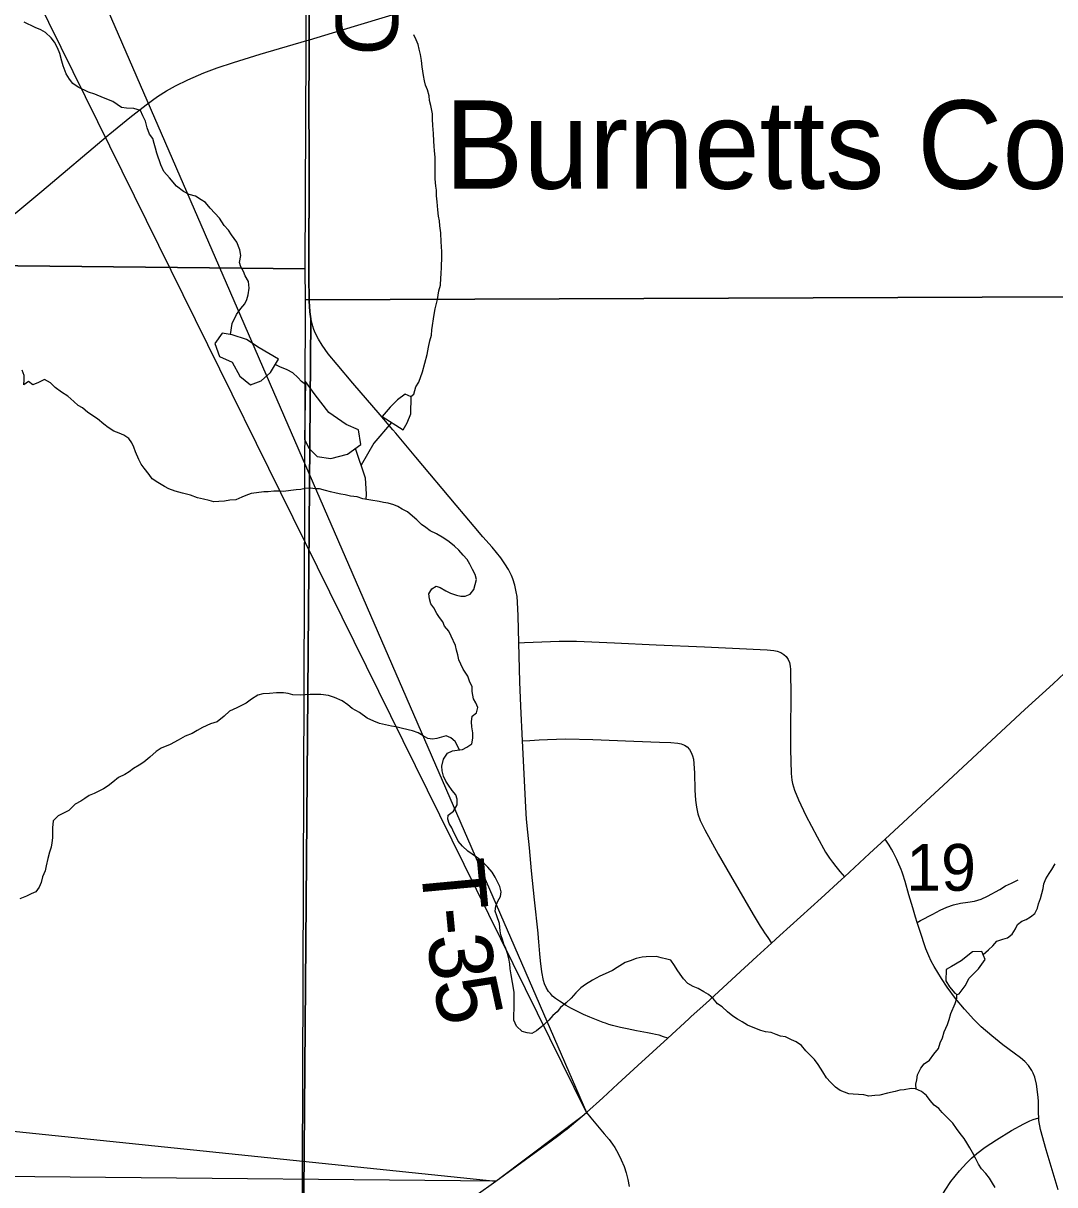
# Model space of a CAD drawing. Extents: x 0 to 34, y 0 to 22.
# Drawn here: x 5.524 to 6.446, y 17.466 to 18.505 of the extents above; entities that cross this region are included whole.
import ezdxf

# ---------------------------------------------------------------- set-up
doc = ezdxf.new("R2010")
doc.units = 0
for name, color, linetype in [('Default', 7, 'Continuous'), ('GM_X_Minor_Lake', 7, 'Continuous'), ('GM_X_Minor_River', 7, 'Continuous'), ('GM_X_Section', 7, 'Continuous'), ('GM_X_Section_Text', 7, 'Continuous'), ('GM_X_State_Route', 7, 'Continuous'), ('GM_X_Township_Road', 7, 'Continuous'), ('GM_X_Township_Road_Text', 7, 'Continuous'), ('GM_X_Unincorporated_Text', 7, 'Continuous'), ('SH_Text', 7, 'Continuous')]:
    doc.layers.add(name, color=color, linetype=linetype)

msp = doc.modelspace()

# ---------------------------------------------------------------- linework, layer by layer
at = {"layer": 'Default'}
for points in [[(5.415, 18.9404), (6.0271, 17.5311), (5.415, 18.772)], [(4.804, 17.5881), (5.946, 17.4698), (4.804, 17.4805)]]:
    msp.add_lwpolyline(points, close=True, dxfattribs=at)
at = {"layer": 'GM_X_Minor_Lake'}
for points in [[(5.7517, 18.2048), (5.7346, 18.2149), (5.7231, 18.2224), (5.7102, 18.2265), (5.7015, 18.2279), (5.6948, 18.2188), (5.699, 18.2071), (5.7104, 18.2022), (5.7173, 18.1897), (5.7268, 18.1819), (5.7363, 18.1853), (5.7446, 18.193)], [(5.7446, 18.193), (5.7517, 18.2048)], [(5.7749, 18.1329), (5.7791, 18.125), (5.7864, 18.1178), (5.7985, 18.116), (5.8136, 18.1199), (5.8253, 18.1284), (5.8233, 18.1416), (5.8123, 18.1465), (5.7967, 18.157), (5.7845, 18.1728), (5.776, 18.1849)], [(5.776, 18.1849), (5.7749, 18.1329)], [(5.8631, 18.1415), (5.8668, 18.148), (5.8702, 18.156), (5.8704, 18.1712), (5.8651, 18.1734), (5.8583, 18.1684), (5.8516, 18.1619), (5.8444, 18.1535)], [(5.8444, 18.1535), (5.8631, 18.1415)], [(6.3604, 17.6371), (6.3657, 17.6444), (6.3694, 17.6512), (6.3777, 17.6596), (6.3837, 17.668), (6.3806, 17.6752), (6.3723, 17.6748), (6.3621, 17.6667), (6.3534, 17.6617), (6.3489, 17.659), (6.3486, 17.6488), (6.3517, 17.6435)], [(6.3517, 17.6435), (6.3565, 17.6377), (6.3585, 17.6367), (6.3604, 17.6371)]]:
    msp.add_lwpolyline(points, dxfattribs=at)
at = {"layer": 'GM_X_Minor_River'}
for points in [[(5.7088, 18.2267), (5.7104, 18.2367), (5.7141, 18.2447), (5.7182, 18.2501), (5.7216, 18.2543), (5.7234, 18.2582), (5.7245, 18.2623), (5.7256, 18.2684), (5.7248, 18.2741), (5.722, 18.2794), (5.7205, 18.2832), (5.7181, 18.2873), (5.7169, 18.2911), (5.718, 18.2976), (5.7172, 18.3025), (5.7144, 18.3093), (5.7098, 18.3161), (5.707, 18.3202), (5.7032, 18.3244), (5.6989, 18.3308), (5.6908, 18.3398), (5.6866, 18.345), (5.6827, 18.3473), (5.6777, 18.3506), (5.672, 18.3521), (5.6667, 18.3546), (5.6605, 18.3595), (5.6543, 18.367), (5.6493, 18.3726), (5.6466, 18.3787), (5.643, 18.3889), (5.6418, 18.3934), (5.6406, 18.3976), (5.6394, 18.4021), (5.6363, 18.4059), (5.6344, 18.4116), (5.6328, 18.4176), (5.6304, 18.4225), (5.6284, 18.4271), (5.6223, 18.4289), (5.6159, 18.4292), (5.6113, 18.4299), (5.6036, 18.4351), (5.5952, 18.4384), (5.5876, 18.4417), (5.5818, 18.4435), (5.5727, 18.448), (5.568, 18.4513), (5.565, 18.4551), (5.5618, 18.46), (5.5591, 18.4672), (5.5579, 18.4713), (5.5563, 18.4781), (5.5543, 18.4831), (5.5516, 18.4883), (5.5485, 18.4921), (5.5435, 18.497), (5.5393, 18.4992), (5.5343, 18.5014), (5.5244, 18.5062)], [(5.8702, 18.1713), (5.8729, 18.1735), (5.8747, 18.18), (5.8773, 18.1842), (5.8806, 18.1934), (5.8846, 18.209), (5.886, 18.2155), (5.8871, 18.2212), (5.8885, 18.2262), (5.8889, 18.2311), (5.891, 18.2448), (5.892, 18.2498), (5.8938, 18.2582), (5.8952, 18.2658), (5.8967, 18.2711), (5.897, 18.2772), (5.8973, 18.281), (5.8976, 18.2871), (5.8979, 18.2962), (5.8978, 18.3004), (5.8974, 18.3057), (5.8973, 18.3095), (5.8969, 18.3178), (5.896, 18.3239), (5.8956, 18.3285), (5.8948, 18.3326), (5.8943, 18.3383), (5.8935, 18.3455), (5.893, 18.3508), (5.8929, 18.3558), (5.8925, 18.3596), (5.892, 18.366), (5.8919, 18.3808), (5.8918, 18.3854), (5.8913, 18.3911), (5.8909, 18.3952), (5.8908, 18.3998), (5.8904, 18.4066), (5.8899, 18.4138), (5.8894, 18.4195), (5.8894, 18.4241), (5.8881, 18.4317), (5.8869, 18.4362), (5.8865, 18.4404), (5.8849, 18.4457), (5.8833, 18.4498), (5.8822, 18.4536), (5.8813, 18.4586), (5.8801, 18.4661), (5.8796, 18.4718), (5.8788, 18.4771), (5.8776, 18.4821), (5.8768, 18.4862), (5.8748, 18.4904), (5.8729, 18.4949)], [(5.776, 18.182), (5.7723, 18.1847), (5.7692, 18.1885), (5.7646, 18.1926), (5.7596, 18.1952), (5.7531, 18.1978), (5.7488, 18.2)], [(5.8964, 18.0006), (5.9014, 17.9977), (5.9056, 17.9954), (5.911, 17.9936), (5.9148, 17.9929), (5.9186, 17.993), (5.9231, 17.9945), (5.9265, 17.9988), (5.9287, 18.0079), (5.9275, 18.0121), (5.9251, 18.0166), (5.9228, 18.0215), (5.9204, 18.0257), (5.917, 18.0294), (5.9131, 18.0339), (5.9092, 18.0377), (5.9043, 18.0414), (5.8996, 18.0447), (5.8931, 18.0485), (5.8874, 18.0514), (5.8835, 18.0544), (5.8797, 18.057), (5.8755, 18.0611), (5.8716, 18.0645), (5.867, 18.0682), (5.8624, 18.0708), (5.8586, 18.0731), (5.8548, 18.0745), (5.8498, 18.076), (5.8456, 18.0767), (5.8418, 18.0774), (5.8342, 18.0788), (5.8273, 18.0799), (5.822, 18.0817), (5.8162, 18.0824), (5.8113, 18.0835), (5.8075, 18.0842), (5.8033, 18.0849), (5.7983, 18.0863), (5.7937, 18.0874), (5.7884, 18.0888), (5.7846, 18.0888), (5.7804, 18.0895), (5.7755, 18.0891), (5.7717, 18.0882), (5.7675, 18.0878), (5.7629, 18.0874), (5.7561, 18.0865), (5.7523, 18.0868), (5.7477, 18.0868), (5.7424, 18.0863), (5.7386, 18.0863), (5.7322, 18.0854), (5.7272, 18.0846), (5.7227, 18.083), (5.7189, 18.0815), (5.7136, 18.0791), (5.7083, 18.0787), (5.7034, 18.0778), (5.6984, 18.0774), (5.6939, 18.0773), (5.6897, 18.0784), (5.6847, 18.0795), (5.6794, 18.0809), (5.6732, 18.0831), (5.666, 18.0849), (5.6595, 18.0867), (5.6538, 18.0889), (5.6499, 18.0908), (5.6438, 18.0945), (5.6388, 18.0979), (5.6361, 18.1016), (5.6318, 18.1073), (5.6291, 18.111), (5.6268, 18.1152), (5.624, 18.122), (5.6225, 18.1261), (5.6205, 18.1299), (5.6178, 18.1337), (5.6136, 18.1367), (5.6094, 18.1385), (5.6044, 18.1403), (5.5994, 18.1437), (5.5956, 18.1467), (5.5898, 18.1515), (5.5814, 18.1571), (5.5764, 18.1612), (5.5725, 18.1635), (5.5687, 18.1668), (5.5633, 18.1717), (5.5576, 18.1754), (5.5522, 18.1795), (5.5479, 18.1836), (5.5426, 18.1866), (5.5373, 18.1839), (5.532, 18.1819), (5.5282, 18.1849), (5.524, 18.1818), (5.5243, 18.1864), (5.5243, 18.1902), (5.5227, 18.1951)], [(5.8528, 18.1481), (5.837, 18.1296), (5.8257, 18.1101)], [(5.8303, 18.0794), (5.8305, 18.0844), (5.8297, 18.0984), (5.8206, 18.125)], [(6.022, 17.6426), (6.0175, 17.638), (6.0134, 17.6334), (6.0089, 17.6291), (6.004, 17.6249), (6.001, 17.621), (5.9972, 17.6179), (5.9935, 17.6137), (5.9871, 17.6079), (5.9826, 17.6041), (5.9784, 17.6017), (5.9742, 17.6024), (5.9697, 17.6035), (5.9647, 17.6084), (5.9623, 17.6137), (5.9622, 17.619), (5.9626, 17.6232), (5.9624, 17.6388), (5.9611, 17.6475), (5.9599, 17.6543), (5.959, 17.6596), (5.9586, 17.6642), (5.9578, 17.6687), (5.9566, 17.6732), (5.955, 17.6778), (5.9534, 17.6816), (5.9522, 17.6857), (5.9507, 17.6899), (5.9499, 17.6937), (5.9494, 17.7001), (5.947, 17.7069), (5.9454, 17.7111), (5.9461, 17.7157), (5.948, 17.7202), (5.9502, 17.7244), (5.9509, 17.7286), (5.9497, 17.7332), (5.9454, 17.7415), (5.9427, 17.746), (5.9388, 17.7505), (5.9331, 17.7565), (5.9288, 17.7595), (5.925, 17.7621), (5.9212, 17.7647), (5.9162, 17.7692), (5.9123, 17.7737), (5.9107, 17.7775), (5.9084, 17.7816), (5.9068, 17.7858), (5.9045, 17.7895), (5.9033, 17.7933), (5.9036, 17.7971), (5.9081, 17.8006), (5.9115, 17.8064), (5.9114, 17.8113), (5.9102, 17.8151), (5.9071, 17.8192), (5.9037, 17.8237), (5.9013, 17.8275), (5.8994, 17.832), (5.8982, 17.8366), (5.8977, 17.8407), (5.8992, 17.8472), (5.9029, 17.8526), (5.9074, 17.8545), (5.9116, 17.855), (5.9162, 17.8558), (5.9203, 17.8578), (5.9245, 17.8608), (5.9256, 17.8658), (5.9255, 17.8707), (5.9247, 17.876), (5.9242, 17.8806), (5.9249, 17.8855), (5.9287, 17.8886), (5.9301, 17.8932), (5.9282, 17.8974), (5.9262, 17.9011), (5.925, 17.9076), (5.925, 17.9118), (5.9226, 17.9167), (5.921, 17.9212), (5.9168, 17.9276), (5.9148, 17.9321), (5.9129, 17.9359), (5.912, 17.9405), (5.9108, 17.9446), (5.91, 17.9488), (5.9061, 17.9571), (5.9042, 17.9616), (5.9003, 17.9661), (5.8987, 17.9699), (5.8956, 17.9737), (5.8933, 17.9774), (5.8906, 17.9823), (5.8879, 17.9861), (5.8867, 17.9906), (5.8862, 17.9948), (5.8888, 17.9994), (5.8926, 18.0017), (5.8964, 18.0006)], [(5.9136, 17.8553), (5.9096, 17.8629), (5.9058, 17.8663), (5.9016, 17.8681), (5.8932, 17.8657), (5.8894, 17.8649), (5.8852, 17.8656), (5.881, 17.8679), (5.8768, 17.8705), (5.8715, 17.8723), (5.8676, 17.8734), (5.8615, 17.8748), (5.8566, 17.8759), (5.8528, 17.8766), (5.8474, 17.8777), (5.8421, 17.8791), (5.8371, 17.881), (5.831, 17.8839), (5.8241, 17.8888), (5.8176, 17.8925), (5.8137, 17.8958), (5.8087, 17.8992), (5.8019, 17.9021), (5.7965, 17.904), (5.7897, 17.905), (5.7801, 17.9049), (5.771, 17.9044), (5.7646, 17.9047), (5.7604, 17.9058), (5.7562, 17.9065), (5.7501, 17.9064), (5.7436, 17.9059), (5.7379, 17.9055), (5.7334, 17.9043), (5.7277, 17.9008), (5.7228, 17.8973), (5.7145, 17.893), (5.7081, 17.8899), (5.7032, 17.8856), (5.6968, 17.8806), (5.6911, 17.8786), (5.6839, 17.8755), (5.679, 17.8728), (5.6745, 17.87), (5.6684, 17.8677), (5.662, 17.8642), (5.6548, 17.8603), (5.6469, 17.8568), (5.6424, 17.854), (5.6367, 17.849), (5.6315, 17.8444), (5.6273, 17.8417), (5.622, 17.8386), (5.6183, 17.8359), (5.6145, 17.8335), (5.6088, 17.8308), (5.6036, 17.8266), (5.5994, 17.8231), (5.5953, 17.8207), (5.5911, 17.8184), (5.587, 17.8165), (5.5824, 17.8145), (5.5786, 17.8118), (5.5749, 17.8095), (5.57, 17.8067), (5.5643, 17.8013), (5.559, 17.7986), (5.5549, 17.7963), (5.5504, 17.792), (5.5497, 17.7856), (5.5498, 17.7768), (5.5491, 17.7723), (5.5484, 17.7685), (5.5469, 17.7639), (5.5455, 17.7582), (5.5441, 17.7517), (5.543, 17.7471), (5.5408, 17.7418), (5.5397, 17.7368), (5.5378, 17.7326), (5.5349, 17.7284), (5.5307, 17.7268), (5.5265, 17.7245), (5.5205, 17.7221)], [(6.3818, 17.6723), (6.3867, 17.6767), (6.3904, 17.6802), (6.3942, 17.6844), (6.3995, 17.686), (6.4037, 17.6872), (6.4078, 17.6907), (6.4108, 17.6953), (6.4126, 17.6991), (6.4164, 17.7022), (6.4202, 17.7038), (6.4243, 17.7061), (6.4281, 17.7092), (6.4303, 17.7138), (6.4314, 17.7176), (6.4332, 17.7225), (6.4343, 17.7271), (6.4354, 17.7313), (6.4361, 17.7355), (6.438, 17.7401), (6.4409, 17.7447), (6.4432, 17.7485), (6.4461, 17.7535)], [(6.3925, 17.4641), (6.3902, 17.4678), (6.3874, 17.4724), (6.3843, 17.4765), (6.3805, 17.4806), (6.3778, 17.4848), (6.375, 17.4904), (6.3723, 17.4953), (6.37, 17.4995), (6.3672, 17.504), (6.3649, 17.5078), (6.3614, 17.5123), (6.358, 17.5168), (6.3548, 17.5217), (6.3452, 17.5311), (6.3421, 17.5348), (6.3379, 17.5378), (6.3344, 17.5419), (6.3313, 17.5464), (6.3267, 17.5498), (6.3214, 17.5524), (6.3175, 17.5527), (6.3111, 17.5515), (6.3073, 17.5511), (6.3031, 17.5499), (6.2963, 17.5483), (6.2895, 17.5466), (6.2849, 17.5462), (6.2796, 17.5457), (6.275, 17.5468), (6.2705, 17.5471), (6.2655, 17.5475), (6.2617, 17.5478), (6.2541, 17.5507), (6.2498, 17.5537), (6.2452, 17.5582), (6.2417, 17.562), (6.2386, 17.5676), (6.2344, 17.574), (6.2309, 17.5785), (6.227, 17.5827), (6.2232, 17.5864), (6.2193, 17.5909), (6.2147, 17.5943), (6.2105, 17.5961), (6.2051, 17.5987), (6.2006, 17.5994), (6.1967, 17.6009), (6.1922, 17.6027), (6.1872, 17.6034), (6.183, 17.6045), (6.1761, 17.607), (6.1712, 17.6093), (6.1665, 17.6122), (6.1623, 17.6145), (6.1581, 17.6174), (6.1531, 17.6212), (6.1485, 17.6257), (6.1443, 17.6283), (6.1404, 17.6332), (6.1362, 17.6365), (6.132, 17.6391), (6.127, 17.6421), (6.1224, 17.6439), (6.1178, 17.6465), (6.1139, 17.6507), (6.1109, 17.6548), (6.1081, 17.6586), (6.1058, 17.6627), (6.1027, 17.6672), (6.0989, 17.6683), (6.0939, 17.6694), (6.0897, 17.6705), (6.0806, 17.6703), (6.0768, 17.6699), (6.0715, 17.6687), (6.0662, 17.6667), (6.0617, 17.6652), (6.0545, 17.6609), (6.0503, 17.6582), (6.0439, 17.655), (6.039, 17.6531), (6.0326, 17.6496), (6.0262, 17.6457), (6.022, 17.6426)], [(6.322, 17.5521), (6.3217, 17.5566), (6.3224, 17.5604), (6.3231, 17.5649), (6.3261, 17.5707), (6.3291, 17.5745), (6.334, 17.578), (6.3377, 17.5834), (6.3418, 17.5884), (6.3433, 17.5933), (6.3455, 17.5979), (6.3469, 17.6032), (6.3499, 17.6097), (6.3514, 17.6143), (6.3528, 17.6197), (6.3569, 17.6285), (6.3583, 17.6334), (6.3583, 17.6368)]]:
    msp.add_lwpolyline(points, dxfattribs=at)
at = {"layer": 'GM_X_Section'}
for points in [[(4.7796, 18.772), (4.7762, 18.2959), (5.7756, 18.2855), (5.7801, 19.2683), (5.7798, 19.3134), (5.415, 19.3104), (5.415, 18.772)], [(5.7801, 19.2683), (6.9057, 19.2783), (6.9105, 18.2623), (5.7758, 18.2578), (5.7756, 18.2855)], [(4.804, 17.2765), (5.7727, 17.3042), (5.7758, 18.2578), (5.7756, 18.2855), (4.7762, 18.2959), (4.7636, 17.5881), (4.804, 17.5881)], [(5.7758, 18.2578), (6.9105, 18.2623), (6.9237, 17.2428), (5.7724, 17.2281), (5.7727, 17.3042)]]:
    msp.add_lwpolyline(points, close=True, dxfattribs=at)
at = {"layer": 'GM_X_State_Route'}
for points in [[(5.7794, 18.4904), (5.8068, 18.4986), (5.8633, 18.5157), (5.9049, 18.5284), (5.9494, 18.5421), (6.0059, 18.5594), (6.0801, 18.5824), (6.163, 18.6084), (6.2104, 18.6235), (6.2577, 18.6388), (6.311, 18.6557), (6.3939, 18.682), (6.4082, 18.6865)], [(5.6011, 18.4063), (5.6187, 18.4209), (5.6335, 18.4323), (5.6436, 18.4396), (5.6515, 18.4446), (5.6596, 18.4491), (5.6708, 18.4546), (5.6851, 18.4608), (5.6968, 18.4652), (5.7116, 18.4702), (5.7353, 18.4774), (5.7771, 18.4897), (5.7794, 18.4904)], [(5.4118, 18.2609), (5.431, 18.2733), (5.4645, 18.2958), (5.482, 18.3085), (5.4993, 18.3216), (5.5188, 18.337), (5.5403, 18.3549), (5.5996, 18.405), (5.6011, 18.4063)], [(6.1187, 17.6149), (6.1209, 17.6169), (6.1338, 17.6285), (6.1451, 17.6389), (6.1611, 17.6536), (6.1794, 17.6705), (6.1926, 17.6825), (6.2001, 17.6893), (6.2369, 17.7228), (6.2553, 17.7395), (6.2578, 17.7418), (6.2802, 17.7628), (6.2942, 17.7756), (6.3305, 17.8091), (6.3465, 17.8238), (6.385, 17.8598), (6.4192, 17.8915), (6.4443, 17.9146), (6.4648, 17.9336)], [(5.7738, 17.3471), (5.7846, 17.3549), (5.8251, 17.3837), (5.8757, 17.4196), (5.946, 17.4698), (5.9838, 17.4971), (5.9945, 17.5049), (6.0036, 17.5117), (6.0066, 17.514), (6.0098, 17.5165), (6.0233, 17.5278), (6.0271, 17.5311), (6.0418, 17.5443), (6.0552, 17.5567), (6.0732, 17.5733), (6.0998, 17.5976), (6.1187, 17.6149)]]:
    msp.add_lwpolyline(points, dxfattribs=at)
at = {"layer": 'GM_X_Township_Road'}
for points in [[(5.7794, 18.4904), (5.7795, 18.5137), (5.7795, 18.5789), (5.7794, 18.6565), (5.7793, 18.703), (5.7792, 18.7276), (5.779, 18.7589), (5.7792, 18.7962), (5.7792, 18.8145)], [(5.7793, 18.5142), (5.7792, 18.4909), (5.7791, 18.4771), (5.779, 18.4305), (5.7792, 18.3902), (5.7793, 18.356), (5.7789, 18.3064), (5.7788, 18.2915), (5.7789, 18.2795), (5.7793, 18.2565), (5.7794, 18.2521), (5.7799, 18.2471), (5.7807, 18.2409), (5.7736, 17.3477)], [(5.7736, 17.3477), (5.7807, 18.2409), (5.7799, 18.2471), (5.7794, 18.2521), (5.7793, 18.2565), (5.7789, 18.2795), (5.7788, 18.2915), (5.7789, 18.3064), (5.7793, 18.356), (5.7792, 18.3902), (5.779, 18.4305), (5.7791, 18.4771), (5.7792, 18.4909), (5.7793, 18.5142)], [(5.7809, 18.2403), (5.7801, 18.2466), (5.7796, 18.2516), (5.7795, 18.256), (5.7791, 18.279), (5.779, 18.291), (5.7791, 18.3058), (5.7795, 18.3555), (5.7794, 18.3896), (5.7792, 18.43), (5.7793, 18.4765), (5.7794, 18.4904)], [(5.8541, 18.1416), (5.8426, 18.1551), (5.8182, 18.1834), (5.8041, 18.1999), (5.7962, 18.2096), (5.7908, 18.2173), (5.7875, 18.2226), (5.7846, 18.2283), (5.7834, 18.2312), (5.7824, 18.2342), (5.7809, 18.2403)], [(5.9666, 17.9511), (5.9661, 17.9754), (5.9656, 17.9876), (5.9651, 17.9925), (5.9644, 17.9967), (5.9632, 18.0027), (5.9614, 18.0085), (5.9602, 18.0113), (5.9575, 18.0168), (5.9541, 18.0219), (5.9505, 18.027), (5.9428, 18.0366), (5.9346, 18.0459), (5.9266, 18.0552), (5.9107, 18.0742), (5.8747, 18.1171), (5.8567, 18.1385), (5.8541, 18.1416)], [(5.9666, 17.9511), (5.9717, 17.9513), (6.0026, 17.9525), (6.0181, 17.9525), (6.0522, 17.951), (6.0894, 17.9493), (6.1328, 17.9475), (6.1576, 17.9465), (6.1886, 17.945), (6.1948, 17.9444), (6.1978, 17.9437), (6.2008, 17.9426), (6.2036, 17.9408), (6.2056, 17.939), (6.2076, 17.9362), (6.2086, 17.9334), (6.2092, 17.9304), (6.2096, 17.9273), (6.2097, 17.9242), (6.2098, 17.9056), (6.2097, 17.8715), (6.2097, 17.856), (6.2102, 17.8343), (6.2108, 17.8282), (6.2114, 17.8252), (6.2131, 17.8193), (6.2166, 17.8107), (6.2232, 17.7967), (6.2334, 17.7775), (6.241, 17.764), (6.2445, 17.7585), (6.247, 17.7551), (6.25, 17.7511), (6.2537, 17.7465), (6.2578, 17.7418)], [(5.97, 17.8636), (5.9685, 17.8946), (5.9676, 17.9163), (5.9666, 17.9511)], [(5.97, 17.8636), (5.9764, 17.8639), (5.9848, 17.8643), (5.9924, 17.8647), (6.0002, 17.865), (6.0087, 17.8652), (6.0329, 17.8648), (6.0694, 17.8631), (6.0924, 17.8623), (6.1025, 17.8619), (6.1087, 17.8614), (6.1118, 17.8608), (6.1147, 17.8597), (6.1172, 17.858), (6.1193, 17.8558), (6.1209, 17.8531), (6.122, 17.8502), (6.1227, 17.8472), (6.1236, 17.835), (6.1239, 17.8195), (6.1246, 17.8103), (6.1254, 17.8041), (6.1268, 17.7981), (6.1289, 17.7922), (6.1329, 17.7838), (6.145, 17.762), (6.156, 17.7432), (6.1763, 17.7082), (6.1824, 17.6978), (6.1848, 17.6941), (6.1864, 17.6917), (6.1892, 17.6875), (6.1926, 17.6825)], [(6.0998, 17.5976), (6.0959, 17.5989), (6.0921, 17.6002), (6.089, 17.6009), (6.0862, 17.6016), (6.0817, 17.6024), (6.0719, 17.6041), (6.0634, 17.6058), (6.0577, 17.607), (6.0541, 17.6079), (6.0503, 17.6089), (6.0471, 17.6099), (6.0442, 17.6109), (6.0422, 17.6116), (6.036, 17.6141), (6.0302, 17.6163), (6.0245, 17.6188), (6.0132, 17.6244), (6.0089, 17.6267), (6.0029, 17.6307), (5.9994, 17.633), (5.9967, 17.6353), (5.9949, 17.6374), (5.9933, 17.6393), (5.991, 17.643), (5.9897, 17.6463), (5.9886, 17.6492), (5.9871, 17.6568), (5.986, 17.6668), (5.9855, 17.6731), (5.9845, 17.6838), (5.9843, 17.6869), (5.9839, 17.6914), (5.9807, 17.7213), (5.9781, 17.7473), (5.9761, 17.7678), (5.9747, 17.7818), (5.9736, 17.7933), (5.9732, 17.7984), (5.9728, 17.8041), (5.97, 17.8636)], [(6.3228, 17.701), (6.3213, 17.7057), (6.3189, 17.7141), (6.3154, 17.7259), (6.312, 17.7378), (6.3101, 17.7442), (6.3094, 17.746), (6.3086, 17.7483), (6.3056, 17.7553), (6.3047, 17.7574), (6.3015, 17.7638), (6.3, 17.7665), (6.2979, 17.7701), (6.2961, 17.7728), (6.2942, 17.7756)], [(6.3228, 17.701), (6.3259, 17.7028), (6.3369, 17.7086), (6.3434, 17.7121), (6.3494, 17.7148), (6.3553, 17.7169), (6.3616, 17.7184), (6.3682, 17.7192), (6.3742, 17.7202), (6.3772, 17.721), (6.3801, 17.722), (6.3857, 17.7246), (6.3966, 17.7306), (6.4019, 17.7337), (6.4071, 17.7363), (6.4131, 17.7392)], [(6.4315, 17.5264), (6.4313, 17.5307), (6.4312, 17.5416), (6.4307, 17.5472), (6.4294, 17.5565), (6.4279, 17.5626), (6.4266, 17.5664), (6.4254, 17.5687), (6.4225, 17.5732), (6.4192, 17.5766), (6.4152, 17.5799), (6.4096, 17.5841), (6.3994, 17.5917), (6.3896, 17.5996), (6.3802, 17.6078), (6.3735, 17.6143), (6.3651, 17.6236), (6.3572, 17.6332), (6.3498, 17.6432), (6.3445, 17.6509), (6.338, 17.6616), (6.3354, 17.6665), (6.3332, 17.6712), (6.3306, 17.6776), (6.3251, 17.694), (6.3228, 17.701)], [(6.0271, 17.5311), (6.0311, 17.5264), (6.0431, 17.5121), (6.0474, 17.5069), (6.0488, 17.505), (6.0504, 17.5028), (6.0524, 17.4998), (6.0555, 17.4944), (6.0581, 17.4887), (6.0607, 17.4827), (6.0625, 17.4771), (6.0642, 17.4711), (6.0652, 17.465)], [(6.3379, 17.4378), (6.3381, 17.4389), (6.3398, 17.4449), (6.342, 17.4507), (6.3447, 17.4563), (6.3478, 17.4617), (6.353, 17.4693), (6.3608, 17.479), (6.367, 17.4859), (6.3714, 17.4903), (6.3761, 17.4944), (6.3835, 17.5), (6.3939, 17.5068), (6.4072, 17.5149), (6.4181, 17.5209), (6.4237, 17.5236), (6.4267, 17.525), (6.4315, 17.5264)], [(6.4489, 17.462), (6.4443, 17.477), (6.4381, 17.4977), (6.4331, 17.5159), (6.4317, 17.524), (6.4315, 17.5264)]]:
    msp.add_lwpolyline(points, dxfattribs=at)
at = {"layer": 'SH_Text'}
msp.add_line((5.9496, 17.4724), (6.0233, 17.5278), dxfattribs=at)

# ---------------------------------------------------------------- texts
at = {"layer": 'GM_X_Section_Text'}
msp.add_text('19', height=0.04186, rotation=0, dxfattribs=at).set_placement((6.3131, 17.7294))
at = {"layer": 'GM_X_Township_Road_Text'}
for s, height, rotation, p in [('S SMYSER RD', 0.056818, 270, (5.8025, 18.9998)), ('T', 0.0568, 275.339, (5.8786, 17.7549)), ('-', 0.0568, 275.3913, (5.8826, 17.7125)), ('3', 0.0568, 275.6478, (5.8848, 17.689)), ('5', 0.0568, 282.1755, (5.8893, 17.6472))]:
    msp.add_text(s, height=height, rotation=rotation, dxfattribs=at).set_placement(p)
at = {"layer": 'GM_X_Unincorporated_Text'}
msp.add_text('Burnetts Corners', height=0.078977, rotation=0, dxfattribs=at).set_placement((5.9002, 18.3572))

doc.saveas('drawing.dxf')
